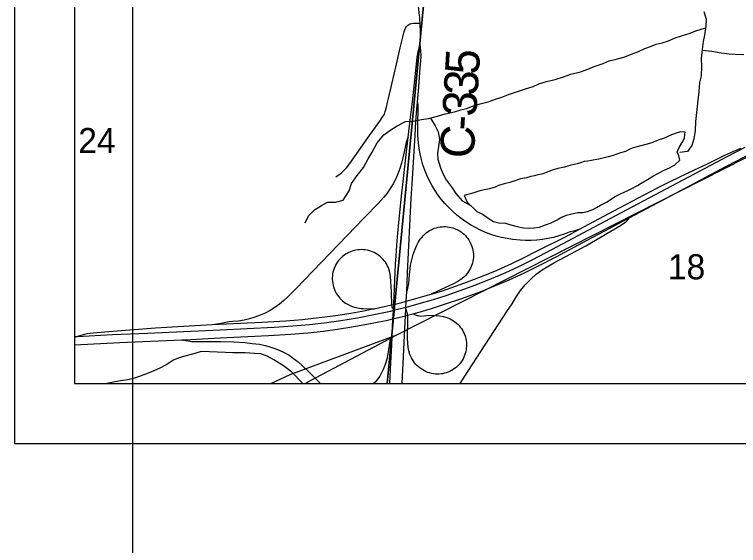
# Model space of a CAD drawing. Extents: x 831 to 1552, y 430 to 870.
# Drawn here: x 1248.77 to 1272.93, y 645.53 to 663.26 of the extents above; entities that cross this region are included whole.
import ezdxf

# ---------------------------------------------------------------- set-up
doc = ezdxf.new("R2010")
doc.units = 0
for name, color, linetype in [('GM_X_Corporation', 7, 'Continuous'), ('GM_X_County_Road', 7, 'Continuous'), ('GM_X_County_Road_Text', 7, 'Continuous'), ('GM_X_Interchange_Ramps', 7, 'Continuous'), ('GM_X_Interstate_Location', 7, 'Continuous'), ('GM_X_Interstate_Route', 7, 'Continuous'), ('GM_X_Minor_Lake', 7, 'Continuous'), ('GM_X_Minor_River', 7, 'Continuous'), ('GM_X_Rail_Line', 7, 'Continuous'), ('GM_X_Section_Text', 7, 'Continuous'), ('GM_X_State_Route', 7, 'Continuous'), ('SC_Scratch1', 7, 'Continuous'), ('SH_Data', 7, 'Continuous')]:
    doc.layers.add(name, color=color, linetype=linetype)

msp = doc.modelspace()

# ---------------------------------------------------------------- linework, layer by layer
at = {"layer": 'GM_X_Corporation'}
for points in [[(1250.766, 669.354), (1250.766, 650.938), (1261.209, 650.938), (1262.858, 668.098), (1261.315, 668.229)], [(1261.209, 650.938), (1280.498, 650.938), (1281.807, 666.237), (1262.858, 668.098)]]:
    msp.add_lwpolyline(points, close=True, dxfattribs=at)
msp.add_lwpolyline([(1250.766, 667.013), (1250.766, 650.938), (1386.766, 650.938)], dxfattribs=at)
at = {"layer": 'GM_X_County_Road'}
msp.add_line((1262.218, 660.335), (1262.261, 660.849), dxfattribs=at)
for points in [[(1262.308, 662.971), (1262.307, 662.987), (1262.301, 663.077), (1262.292, 663.173), (1262.276, 663.31), (1262.259, 663.457), (1262.234, 663.613), (1262.194, 663.818), (1262.121, 664.118), (1262.024, 664.411), (1261.882, 664.754), (1261.803, 664.912), (1261.742, 665.03), (1261.672, 665.156), (1261.584, 665.295), (1261.514, 665.398), (1261.408, 665.546), (1261.322, 665.657), (1261.18, 665.832), (1261.057, 665.977), (1260.846, 666.23), (1260.332, 666.848), (1260.322, 666.861)], [(1259.492, 657.841), (1259.671, 657.967), (1259.764, 658.046), (1259.845, 658.136), (1259.957, 658.284), (1260.566, 659.146), (1260.963, 659.702), (1261.042, 659.826), (1261.113, 659.938), (1261.143, 660.026), (1261.182, 660.172), (1261.215, 660.321), (1261.249, 660.452), (1261.362, 660.936), (1261.517, 661.601), (1261.642, 662.145), (1261.727, 662.508), (1261.774, 662.69), (1261.794, 662.751), (1261.821, 662.809), (1261.856, 662.864), (1261.902, 662.91), (1261.958, 662.945), (1262.021, 662.965), (1262.087, 662.971), (1262.149, 662.971), (1262.308, 662.971)], [(1262.306, 662.293), (1262.315, 662.582), (1262.315, 662.717), (1262.311, 662.895), (1262.308, 662.971)], [(1261.417, 653.42), (1261.424, 653.58), (1261.475, 654.651), (1261.49, 654.928), (1261.51, 655.203), (1261.532, 655.561), (1261.565, 655.959), (1261.596, 656.318), (1261.681, 657.198), (1261.913, 659.166), (1261.99, 659.82), (1262.02, 660.094), (1262.048, 660.348), (1262.195, 661.714), (1262.21, 661.85), (1262.215, 661.895), (1262.227, 661.955), (1262.243, 662.023), (1262.259, 662.09), (1262.306, 662.293)], [(1262.261, 660.849), (1262.301, 661.324), (1262.324, 661.599), (1262.332, 661.725), (1262.337, 661.848), (1262.337, 661.914), (1262.332, 662.029), (1262.306, 662.293)], [(1262.04, 657.594), (1262.137, 659.226), (1262.168, 659.69), (1262.198, 660.099), (1262.218, 660.335)], [(1261.858, 654.006), (1261.887, 654.635), (1262.013, 657.13), (1262.04, 657.594)], [(1261.831, 653.437), (1261.834, 653.486), (1261.842, 653.667), (1261.843, 653.687), (1261.858, 654.006)]]:
    msp.add_lwpolyline(points, dxfattribs=at)
at = {"layer": 'GM_X_Interchange_Ramps'}
for points in [[(1267.602, 656.079), (1267.469, 656.042), (1267.278, 655.989), (1267.112, 655.927), (1266.935, 655.866), (1266.756, 655.816), (1266.573, 655.775), (1266.389, 655.744), (1266.203, 655.724), (1266.016, 655.713), (1265.829, 655.713), (1265.643, 655.721), (1265.394, 655.745), (1265.21, 655.775), (1265.027, 655.813), (1264.846, 655.861), (1264.668, 655.919), (1264.494, 655.986), (1264.322, 656.061), (1264.155, 656.144), (1263.992, 656.236), (1263.834, 656.336), (1263.682, 656.445), (1263.535, 656.561), (1263.395, 656.684), (1263.261, 656.815), (1263.134, 656.952), (1263.014, 657.095), (1262.901, 657.244), (1262.796, 657.399), (1262.7, 657.56), (1262.612, 657.725), (1262.533, 657.894), (1262.463, 658.067), (1262.402, 658.244), (1262.351, 658.424), (1262.309, 658.606), (1262.276, 658.79), (1262.252, 658.976), (1262.234, 659.224), (1262.23, 659.51), (1262.236, 660.212), (1262.236, 660.256), (1262.229, 660.301), (1262.218, 660.335)], [(1261.913, 659.166), (1261.875, 659.086), (1261.843, 658.994), (1261.817, 658.887), (1261.774, 658.675), (1261.734, 658.479), (1261.687, 658.298), (1261.632, 658.12), (1261.567, 657.945), (1261.492, 657.774), (1261.408, 657.607), (1261.312, 657.447), (1261.205, 657.294), (1261.088, 657.149), (1260.921, 656.964), (1260.444, 656.472), (1258.155, 654.096), (1257.891, 653.831), (1257.753, 653.705), (1257.609, 653.586), (1257.457, 653.478), (1257.299, 653.379), (1257.134, 653.292), (1256.963, 653.215), (1256.788, 653.15), (1256.61, 653.095), (1256.428, 653.055), (1256.243, 653.025), (1256.058, 653.003), (1255.932, 652.992), (1255.661, 652.945), (1255.364, 652.892)], [(1261.858, 654.006), (1261.881, 654.065), (1261.91, 654.172), (1261.928, 654.27), (1261.955, 654.574), (1261.972, 654.766), (1261.989, 654.888), (1262.028, 655.07), (1262.078, 655.248), (1262.14, 655.424), (1262.19, 655.537), (1262.246, 655.647), (1262.311, 655.753), (1262.348, 655.803), (1262.43, 655.895), (1262.474, 655.938), (1262.522, 655.977), (1262.572, 656.013), (1262.624, 656.046), (1262.678, 656.075), (1262.734, 656.101), (1262.792, 656.123), (1262.851, 656.142), (1262.911, 656.157), (1262.972, 656.168), (1263.034, 656.175), (1263.095, 656.178), (1263.157, 656.177), (1263.219, 656.172), (1263.28, 656.164), (1263.341, 656.151), (1263.401, 656.135), (1263.459, 656.114), (1263.572, 656.063), (1263.625, 656.032), (1263.677, 655.998), (1263.726, 655.96), (1263.772, 655.92), (1263.816, 655.876), (1263.858, 655.83), (1263.896, 655.781), (1263.932, 655.731), (1263.992, 655.623), (1264.038, 655.508), (1264.055, 655.448), (1264.069, 655.388), (1264.078, 655.327), (1264.084, 655.265), (1264.086, 655.203), (1264.083, 655.142), (1264.077, 655.08), (1264.067, 655.019), (1264.053, 654.959), (1264.035, 654.899), (1264.013, 654.842), (1263.988, 654.785), (1263.959, 654.731), (1263.89, 654.628), (1263.809, 654.535), (1263.765, 654.492), (1263.669, 654.414), (1263.565, 654.346), (1263.402, 654.257), (1263.278, 654.199), (1263.004, 654.078), (1262.837, 654.001), (1262.675, 653.925)], [(1260.776, 653.431), (1260.478, 653.367), (1259.989, 653.275), (1259.497, 653.198), (1258.941, 653.127), (1258.385, 653.069), (1257.826, 653.024), (1257.019, 652.977), (1255.364, 652.892), (1254.41, 652.843), (1253.478, 652.786), (1252.05, 652.671), (1251.39, 652.624), (1251.193, 652.6), (1251.054, 652.562), (1250.873, 652.513)], [(1262.077, 653.27), (1262.173, 653.224), (1262.206, 653.212), (1262.241, 653.204), (1262.288, 653.194), (1262.332, 653.192), (1262.518, 653.21), (1262.705, 653.216), (1262.83, 653.212), (1262.954, 653.2), (1263.077, 653.178), (1263.196, 653.144), (1263.311, 653.096), (1263.366, 653.067), (1263.419, 653.034), (1263.47, 652.999), (1263.564, 652.917), (1263.607, 652.872), (1263.648, 652.824), (1263.684, 652.774), (1263.718, 652.721), (1263.748, 652.666), (1263.774, 652.61), (1263.797, 652.551), (1263.816, 652.492), (1263.831, 652.431), (1263.843, 652.37), (1263.85, 652.308), (1263.854, 652.246), (1263.853, 652.183), (1263.849, 652.121), (1263.841, 652.059), (1263.828, 651.998), (1263.812, 651.938), (1263.792, 651.879), (1263.768, 651.821), (1263.741, 651.765), (1263.71, 651.71), (1263.676, 651.658), (1263.639, 651.608), (1263.598, 651.561), (1263.554, 651.516), (1263.508, 651.475), (1263.459, 651.436), (1263.407, 651.401), (1263.353, 651.37), (1263.297, 651.341), (1263.24, 651.317), (1263.181, 651.296), (1263.121, 651.279), (1263.06, 651.266), (1262.998, 651.257), (1262.936, 651.252), (1262.873, 651.251), (1262.811, 651.255), (1262.749, 651.262), (1262.688, 651.274), (1262.628, 651.29), (1262.568, 651.309), (1262.51, 651.333), (1262.399, 651.39), (1262.295, 651.459), (1262.247, 651.498), (1262.201, 651.541), (1262.157, 651.586), (1262.117, 651.633), (1262.047, 651.736), (1262.017, 651.791), (1261.968, 651.905), (1261.933, 652.024), (1261.909, 652.147), (1261.894, 652.272), (1261.884, 652.459), (1261.895, 653.097), (1261.894, 653.162), (1261.887, 653.219), (1261.883, 653.259), (1261.863, 653.334), (1261.831, 653.437)], [(1254.343, 652.396), (1254.557, 652.358), (1254.684, 652.343), (1254.808, 652.341), (1255.348, 652.342), (1255.652, 652.337), (1256.086, 652.325), (1256.457, 652.302), (1256.704, 652.279), (1256.949, 652.246), (1257.132, 652.21), (1257.252, 652.178), (1257.429, 652.121), (1257.601, 652.052), (1257.769, 651.971), (1257.93, 651.879), (1258.085, 651.776), (1258.233, 651.664), (1258.374, 651.543), (1258.597, 651.328), (1258.985, 650.938)], [(1261.374, 652.518), (1261.33, 652.455), (1261.308, 652.406), (1261.298, 652.354), (1261.256, 652.067), (1261.234, 651.933), (1261.19, 651.753), (1261.137, 651.575), (1261.072, 651.401), (1261.021, 651.289), (1260.961, 651.181), (1260.889, 651.08), (1260.807, 650.988), (1260.761, 650.946), (1260.751, 650.938)]]:
    msp.add_lwpolyline(points, dxfattribs=at)
at = {"layer": 'GM_X_Interstate_Route'}
for p, q in [((1268.471, 656.034), (1269.29, 656.468)), ((1250.766, 652.508), (1250.873, 652.513))]:
    msp.add_line(p, q, dxfattribs=at)
for points in [[(1272.899, 658.385), (1275.459, 659.74), (1276.248, 660.164)], [(1250.873, 652.513), (1252.033, 652.569), (1253.212, 652.622), (1255.632, 652.735), (1257.432, 652.821), (1258.053, 652.861), (1258.611, 652.909), (1259.106, 652.964), (1259.661, 653.041), (1260.215, 653.132), (1260.765, 653.237), (1261.313, 653.357), (1261.415, 653.382), (1261.834, 653.486), (1261.857, 653.491), (1262.278, 653.605), (1262.756, 653.744), (1263.171, 653.877), (1263.642, 654.04), (1264.167, 654.236), (1264.686, 654.444), (1265.144, 654.639), (1265.598, 654.846), (1266.045, 655.065), (1266.708, 655.408), (1268.299, 656.254), (1270.713, 657.536), (1272.579, 658.526), (1273.16, 658.835)], [(1261.379, 653.569), (1261.424, 653.58), (1261.565, 653.613), (1261.691, 653.642), (1261.843, 653.687), (1262.164, 653.78), (1262.628, 653.912), (1262.675, 653.925), (1263.058, 654.036), (1263.487, 654.183), (1263.89, 654.33), (1264.354, 654.508), (1264.873, 654.721), (1265.372, 654.945), (1265.717, 655.108), (1266.262, 655.386), (1267.157, 655.841), (1267.602, 656.079), (1268.967, 656.809), (1270.234, 657.476), (1270.678, 657.699), (1271.466, 658.071), (1271.88, 658.267), (1272.473, 658.558), (1272.88, 658.747), (1273.027, 658.797)], [(1269.29, 656.468), (1271.013, 657.381), (1272.493, 658.171), (1272.899, 658.385)], [(1263.647, 650.938), (1263.78, 651.144), (1265.2, 653.339), (1265.376, 653.596), (1265.504, 653.815), (1265.662, 654.04), (1265.813, 654.229), (1265.999, 654.427), (1266.181, 654.585), (1266.382, 654.732), (1266.549, 654.829), (1266.793, 654.98), (1267.172, 655.181), (1267.834, 655.541), (1268.349, 655.832), (1268.997, 656.213), (1269.142, 656.312), (1269.194, 656.354), (1269.243, 656.405), (1269.29, 656.468)], [(1262.077, 653.27), (1262.194, 653.302), (1262.683, 653.446), (1263.155, 653.594), (1263.668, 653.764), (1264.307, 654.003), (1264.826, 654.209), (1265.283, 654.403), (1265.791, 654.635), (1266.237, 654.852), (1266.843, 655.166), (1267.884, 655.723), (1268.471, 656.034)], [(1261.299, 650.938), (1261.332, 651.633), (1261.36, 652.222), (1261.374, 652.518), (1261.401, 653.097), (1261.414, 653.357), (1261.415, 653.382), (1261.417, 653.42), (1261.389, 653.452), (1261.378, 653.481), (1261.371, 653.526), (1261.367, 653.566), (1261.361, 653.63), (1261.35, 653.914), (1261.348, 654.024), (1261.334, 654.336), (1261.315, 654.522), (1261.293, 654.645), (1261.259, 654.765), (1261.236, 654.823), (1261.21, 654.879), (1261.18, 654.934), (1261.146, 654.986), (1261.109, 655.036), (1261.068, 655.084), (1261.025, 655.129), (1260.979, 655.171), (1260.931, 655.21), (1260.88, 655.247), (1260.827, 655.279), (1260.771, 655.309), (1260.715, 655.335), (1260.656, 655.357), (1260.597, 655.375), (1260.536, 655.39), (1260.474, 655.4), (1260.412, 655.406), (1260.35, 655.409), (1260.288, 655.407), (1260.225, 655.402), (1260.164, 655.392), (1260.103, 655.378), (1260.043, 655.361), (1259.985, 655.339), (1259.928, 655.314), (1259.872, 655.285), (1259.819, 655.252), (1259.718, 655.178), (1259.672, 655.137), (1259.627, 655.093), (1259.586, 655.046), (1259.548, 654.997), (1259.514, 654.945), (1259.483, 654.891), (1259.456, 654.835), (1259.432, 654.777), (1259.413, 654.717), (1259.397, 654.657), (1259.385, 654.596), (1259.378, 654.534), (1259.374, 654.472), (1259.375, 654.409), (1259.379, 654.347), (1259.388, 654.285), (1259.4, 654.224), (1259.417, 654.164), (1259.46, 654.047), (1259.517, 653.936), (1259.551, 653.883), (1259.588, 653.833), (1259.628, 653.785), (1259.671, 653.74), (1259.717, 653.698), (1259.817, 653.624), (1259.926, 653.562), (1260.04, 653.512), (1260.159, 653.474), (1260.282, 653.45), (1260.344, 653.444), (1260.406, 653.442), (1260.616, 653.436), (1260.776, 653.431), (1260.964, 653.472), (1261.354, 653.563)], [(1261.71, 650.938), (1261.754, 651.839), (1261.79, 652.537), (1261.821, 653.202), (1261.831, 653.437)], [(1260.927, 652.994), (1261.168, 653.04), (1261.401, 653.097), (1261.73, 653.177), (1261.821, 653.202), (1261.887, 653.219), (1262.077, 653.27)], [(1254.343, 652.396), (1254.644, 652.409), (1255.629, 652.461), (1257.246, 652.537), (1257.991, 652.581), (1258.559, 652.629), (1259.072, 652.685), (1259.548, 652.749), (1260.028, 652.825), (1260.653, 652.941), (1260.927, 652.994)], [(1250.766, 652.232), (1252.278, 652.305), (1254.343, 652.396)]]:
    msp.add_lwpolyline(points, dxfattribs=at)
at = {"layer": 'GM_X_Minor_Lake'}
for points in [[(1271.147, 659.26), (1271.153, 659.33), (1271.002, 659.347), (1270.888, 659.311), (1270.698, 659.237), (1270.432, 659.119), (1270.25, 659.061), (1270.037, 658.973), (1269.84, 658.922), (1269.635, 658.864), (1269.415, 658.806), (1269.302, 658.769), (1269.157, 658.688), (1268.99, 658.637), (1268.876, 658.6), (1268.747, 658.556), (1268.58, 658.505), (1268.406, 658.462), (1268.277, 658.426), (1268.14, 658.405), (1268.027, 658.383), (1267.906, 658.362), (1267.784, 658.348), (1267.663, 658.312), (1267.549, 658.275), (1267.307, 658.218), (1267.124, 658.167), (1266.905, 658.117), (1266.715, 658.058), (1266.601, 658.014), (1266.373, 657.926), (1266.237, 657.905), (1266.123, 657.876), (1266.002, 657.847), (1265.858, 657.811), (1265.653, 657.776), (1265.463, 657.71), (1265.296, 657.651), (1265.114, 657.608), (1264.925, 657.55), (1264.811, 657.498), (1264.621, 657.44), (1264.439, 657.404), (1264.265, 657.361), (1264.098, 657.31), (1263.782, 657.22)], [(1263.782, 657.22), (1263.875, 656.994), (1264.203, 656.687), (1264.414, 656.586), (1264.579, 656.463), (1264.751, 656.347), (1264.939, 656.299), (1265.159, 656.289), (1265.339, 656.241), (1265.543, 656.186), (1265.754, 656.138), (1265.943, 656.128), (1266.102, 656.133), (1266.291, 656.161), (1266.496, 656.235), (1266.686, 656.3), (1266.884, 656.404), (1267.005, 656.486), (1267.195, 656.559), (1267.37, 656.603), (1267.574, 656.646), (1267.741, 656.651), (1267.892, 656.68), (1268.075, 656.753), (1268.196, 656.82), (1268.326, 656.894), (1268.554, 657.005), (1268.79, 657.169), (1269.019, 657.288), (1269.216, 657.376), (1269.346, 657.443), (1269.558, 657.546), (1269.688, 657.628), (1269.894, 657.754), (1270.092, 657.873), (1270.259, 657.962), (1270.472, 658.073), (1270.632, 658.139), (1270.807, 658.243), (1270.975, 658.4), (1270.939, 658.545), (1270.888, 658.659), (1270.95, 658.817), (1271.058, 658.983), (1271.135, 659.134), (1271.147, 659.26)]]:
    msp.add_lwpolyline(points, dxfattribs=at)
at = {"layer": 'GM_X_Minor_River'}
for points in [[(1271.777, 663.362), (1271.85, 663.103), (1271.839, 662.868), (1271.798, 662.573), (1271.75, 662.354), (1271.724, 662.089), (1271.69, 661.787), (1271.694, 661.521), (1271.683, 661.218), (1271.627, 660.992), (1271.608, 660.674), (1271.582, 660.401), (1271.54, 660.091), (1271.523, 659.887), (1271.498, 659.69), (1271.486, 659.387), (1271.445, 659.107), (1271.374, 658.881), (1271.228, 658.685), (1270.978, 658.65)], [(1258.474, 656.309), (1258.577, 656.536), (1258.776, 656.738), (1259.02, 656.886), (1259.21, 656.99), (1259.483, 656.994), (1259.74, 657.059), (1259.941, 657.375), (1260.012, 657.617), (1260.204, 657.887), (1260.412, 658.15), (1260.574, 658.436), (1260.705, 658.669), (1260.868, 658.971), (1261.098, 659.241), (1261.296, 659.39), (1261.54, 659.546), (1261.821, 659.686), (1262.079, 659.698), (1262.351, 659.756), (1262.586, 659.783), (1262.882, 659.871), (1263.147, 659.943), (1263.451, 660.015), (1263.671, 660.073), (1263.86, 660.124), (1264.05, 660.197), (1264.308, 660.278), (1264.574, 660.343), (1264.824, 660.438), (1265.037, 660.504), (1265.257, 660.584), (1265.523, 660.68), (1265.826, 660.782), (1266.084, 660.862), (1266.274, 660.943), (1266.525, 661.024), (1266.813, 661.096), (1267.094, 661.183), (1267.337, 661.271), (1267.655, 661.343), (1267.845, 661.409), (1268.111, 661.527), (1268.415, 661.629), (1268.62, 661.71), (1268.9, 661.783), (1269.105, 661.841), (1269.363, 661.936), (1269.599, 662.024), (1269.804, 662.128), (1269.994, 662.194), (1270.191, 662.267), (1270.381, 662.31), (1270.601, 662.383), (1270.822, 662.487), (1271.034, 662.552), (1271.322, 662.64), (1271.512, 662.713), (1271.832, 662.815)], [(1271.721, 662.065), (1272.041, 662.04), (1272.357, 661.976), (1272.622, 661.95), (1272.825, 661.932), (1273.113, 661.921)], [(1262.654, 659.803), (1262.81, 659.546), (1262.906, 659.347), (1262.956, 659.089), (1262.915, 658.855), (1262.882, 658.635), (1262.902, 658.431), (1262.982, 658.142), (1263.062, 657.951), (1263.173, 657.745), (1263.374, 657.477), (1263.5, 657.279), (1263.709, 657.034), (1263.997, 656.879)], [(1251.778, 650.938), (1251.792, 650.941), (1252.02, 650.984), (1252.301, 651.04), (1252.552, 651.075), (1252.78, 651.132), (1253.093, 651.242), (1253.352, 651.337), (1253.627, 651.462), (1253.818, 651.566), (1254.047, 651.714), (1254.238, 651.795), (1254.466, 651.86), (1254.718, 651.933), (1254.978, 652.012)], [(1258.395, 650.938), (1258.395, 650.938), (1258.014, 651.329), (1257.744, 651.529), (1257.422, 651.73), (1257.197, 651.846), (1256.986, 651.925), (1256.782, 651.942), (1256.465, 651.961), (1256.057, 651.966), (1255.815, 651.977), (1255.543, 651.988), (1255.278, 651.999), (1254.978, 652.012)]]:
    msp.add_lwpolyline(points, dxfattribs=at)
at = {"layer": 'GM_X_Rail_Line'}
for points in [[(1261.527, 652.567), (1284.1, 664.037), (1310.179, 677.801), (1313.677, 679.557), (1320.635, 683.299), (1323.83, 685.434), (1326.948, 687.535)], [(1257.328, 650.938), (1257.968, 651.236), (1261.527, 652.567)], [(1258.469, 650.938), (1258.645, 651.035), (1261.527, 652.567)]]:
    msp.add_lwpolyline(points, dxfattribs=at)
at = {"layer": 'GM_X_State_Route'}
msp.add_line((1268.471, 656.034), (1269.29, 656.468), dxfattribs=at)
for points in [[(1272.899, 658.385), (1275.459, 659.74), (1276.248, 660.164)], [(1269.29, 656.468), (1271.013, 657.381), (1272.493, 658.171), (1272.899, 658.385)], [(1262.077, 653.27), (1262.194, 653.302), (1262.683, 653.446), (1263.155, 653.594), (1263.668, 653.764), (1264.307, 654.003), (1264.826, 654.209), (1265.283, 654.403), (1265.791, 654.635), (1266.237, 654.852), (1266.843, 655.166), (1267.884, 655.723), (1268.471, 656.034)], [(1260.927, 652.994), (1261.168, 653.04), (1261.401, 653.097), (1261.73, 653.177), (1261.821, 653.202), (1261.887, 653.219), (1262.077, 653.27)], [(1254.343, 652.396), (1254.644, 652.409), (1255.629, 652.461), (1257.246, 652.537), (1257.991, 652.581), (1258.559, 652.629), (1259.072, 652.685), (1259.548, 652.749), (1260.028, 652.825), (1260.653, 652.941), (1260.927, 652.994)], [(1250.766, 652.232), (1252.278, 652.305), (1254.343, 652.396)]]:
    msp.add_lwpolyline(points, dxfattribs=at)
at = {"layer": 'SC_Scratch1'}
msp.add_line((1252.705, 666.938), (1252.705, 620.925), dxfattribs=at)
at = {"layer": 'SH_Data'}
for p, q in [((1248.766, 788.938), (1248.766, 648.938)), ((1250.766, 786.938), (1250.766, 650.938)), ((1250.766, 650.938), (1386.766, 650.938)), ((1248.766, 648.938), (1388.766, 648.938))]:
    msp.add_line(p, q, dxfattribs=at)

# ---------------------------------------------------------------- texts
at = {"layer": 'GM_X_County_Road_Text'}
for s, rotation, p in [('5', 86.6657, (1264.266, 661.233)), ('3', 86.4852, (1264.223, 660.531)), ('3', 86.446, (1264.179, 659.831)), ('-', 86.4407, (1264.15, 659.365)), ('C', 86.4304, (1264.092, 658.434))]:
    msp.add_text(s, height=1.136, rotation=rotation, dxfattribs=at).set_placement(p)
at = {"layer": 'GM_X_Interstate_Location'}
for s in ['-', '.', ',']:
    msp.add_text(s, height=0.00379, dxfattribs=at).set_placement((1264.278, 651.882))
msp.add_text('675', height=0.00379, rotation=0, dxfattribs=at).set_placement((1263.121, 651.098))
at = {"layer": 'GM_X_Section_Text'}
for s, p in [('24', (1250.896, 658.633)), ('18', (1270.579, 654.418))]:
    msp.add_text(s, height=0.8371, rotation=0, dxfattribs=at).set_placement(p)

doc.saveas('drawing.dxf')
